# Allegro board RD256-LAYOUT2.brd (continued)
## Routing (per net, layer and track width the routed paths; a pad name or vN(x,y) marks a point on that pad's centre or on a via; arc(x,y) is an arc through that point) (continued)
SIG00045: length 1.3
  BOTTOM w0.3: R28.2 64.7,51.15 R27.1
SIG00046: length 3.9
  TOP w0.3: IC14.4 v2(62.25,52.53)
  BOTTOM w0.3: v2(62.25,52.53) 62.7,52.5 R33.2 R28.1
SIG00047: length 4.2
  TOP w0.3: v2(47,47.9) 46.52,47.9 46,47.38 IC15.4
  BOTTOM w0.3: R30.1 R34.2 v2(47,47.9)
SIG00048: length 1.3
  BOTTOM w0.3: R30.2 49.75,46.65 R35.1
SIG00049: length 1.3
  BOTTOM w0.3: R31.1 49.85,45.15 R35.2
SIG00067: length 4.7
  TOP w0.3: IC18.4 v2(38.57,9.15)
  BOTTOM w0.3: R49.1 39.17,9.75 v2(38.57,9.15) 38.12,9.2 R54.2
SIG00068: length 3.9
  TOP w0.3: R55.2 R51.1 78.45,16.5 78.8,16.15 IC19.4
SIG00069: length 1.2
  TOP w0.3: R56.1 77,14.95 R51.2
SIG00070: length 1.3
  TOP w0.3: R56.2 R52.1
SIG00080: length 2.8
  TOP w0.3: IC25.3 25.45,44.55 C77.2 25.65,44.35 R69.2
SIG00081: length 9.1
  TOP w0.3: R69.1 24.6,41.65 22.6,43.65 v2(22.6,46.1) ; v2(23.25,47.55) 24.01,47.55 24.15,47.69 IC25.6
  BOTTOM w0.3: v2(23.25,47.55) 23.25,46.75 v2(22.6,46.1)
SIG00082: length 1.4
  TOP w0.3: Q8.1 30.35,45.75 IC26.6
SIG00083: length 5.9
  TOP w0.3: IC26.1 27.9,45.75 28.1,45.95 28.1,46.85 26.4,48.55 25.65,48.55 25.45,48.35 IC25.4
SIG00085: length 21.6
  TOP w0.3: R68.1 R73.2 36,39.95 C75.2 36.95,40.1 37.94,41.09 42.17,41.09 43.78,42.7 45.4,42.7 46,42.1 50.7,42.1 51.55,42.95 51.55,43.85 51.2,44.2 IC24.3
SIG00086: length 4.7
  TOP w0.3: v2(51.5,47.8) R66.1 51.6,46.65 51.6,45.7 51.4,45.5 IC24.1
  BOTTOM w0.3: v2(51.5,47.8) 52,47.8 52.25,47.55 R71.2
SIG00087: length 21.4
  TOP w0.3: IC24.4 52.15,44.2 52,44.05 52,43.65 v2(52.35,43.3)
  BOTTOM w0.3: R70.2 39.55,37.75 41.95,37.75 44.45,40.25 44.45,41.25 45.3,42.1 51.15,42.1 v2(52.35,43.3)
SIG00088: length 1.2
  BOTTOM w0.3: R70.1 35.1,40.7 34.02,40.7
SIG00089: length 7.1
  BOTTOM w0.3: IC22.1 32.15,45.85 32.5,45.5 32.5,44.85 33,44.35 R67.1 32.95,43.3 32.95,42.25 C78.2 32.7,40.48 Q10.3
SIG00090: length 2.7
  BOTTOM w0.15: IC22.6 28.65,45.85 28.5,46 28.5,46.75 28.3,46.95 IC27.1
SIG00092: length 12.5
  BOTTOM w0.15: IC23.1 24.68,54.17 21.95,51.45 21.95,49 22.48,48.48 23.07,48.48 23.9,47.64 23.9,46.7 24.15,46.45 IC27.7
SIG00095: length 1.4
  BOTTOM w0.2: IC23.4 28.32,53.33 R72.1
SIG00096: length 5.9
  TOP w0.3: Q7.1 30.7,40.58 R65.1 30.7,42 31,42.3 31.6,42.3 31.85,42.55 D24.1 31.85,45.05 Q8.3
SIG00097: length 11.3
  TOP w0.5: TP39.1 29.05,56 30.08,56 30.6,55.48 v2(30.6,55)
  BOTTOM w0.5: v2(30.6,55) 30.6,54.1 R72.2 31.25,52.35 R74.2 33.85,52.35 Q9.1
SIG00098: length 3
  TOP w0.3: Q7.2 31.07,38.92 31.55,38.45 R68.2
SIG00099: length 4.2
  BOTTOM w0.3: C87.2 46.65,16.5 R79.2 47.75,16 47.95,15.8 48.45,15.8 48.65,15.6 48.65,15.35 48.45,15.15 IC31.3
SIG00100: length 3.4
  BOTTOM w0.15: R79.1 49.25,15.85 49.02,15.62 49.02,14.03 49.2,13.85 IC31.6
SIG00101: length 7.6
  BOTTOM w0.15: IC32.1 53.2,15.15 53.38,15.32 53.38,15.82 53.5,15.95 53.5,16.2
  BOTTOM w0.3: 53.5,16.2 53.5,16.8 53.2,17.1 51.45,17.1 50.9,16.55 50.9,15.55 50.5,15.15 IC31.4
SIG00102: length 3.1
  BOTTOM w0.15: IC32.6 55.4,15.15 56.45,16.2 Q12.1
SIG00104: length 13.8
  TOP w0.3: IC30.3 C86.2 R83.2 60,19.4 60.25,19.65 61.95,19.65 63.25,18.35 63.25,14.7 v2(62,13.45)
  BOTTOM w0.3: R78.1 v2(62,13.45)
SIG00105: length 2.7
  TOP w0.3: IC30.1 59.85,16.05 R76.1 R81.2
SIG00106: length 2.5
  TOP w0.3: IC30.4 54.6,17.35 R80.2
SIG00107: length 1.3
  TOP w0.3: Q14.1 52.67,17.07 R80.1
SIG00108: length 5.7
  TOP w0.3: C88.2 50.62,15.45 Q14.3 51.65,15.93 51.95,15.62 R77.1 IC28.1
SIG00109: length 2.4
  TOP w0.15: IC33.1 52.94,11.25 52.54,11.65 52.15,11.65 51.95,11.45 IC28.6
SIG00111: length 3.9
  TOP w0.3: IC33.7 v2(57.3,10.75)
  BOTTOM w0.2: IC29.1 55.9,9.35 v2(57.3,10.75)
SIG00114: length 1.1
  BOTTOM w0.15: IC29.4 54.17,7.72 R82.1
SIG00115: length 7.3
  BOTTOM w0.15: Q12.3 57.75,14.75 D25.1 58.8,13.85 58.8,11.35 R75.1 59.52,11.25 Q11.1
SIG00116: length 8
  TOP w0.3: TP40.1 56.45,7.8 v2(56.85,7.4)
  BOTTOM w0.5: R82.2 55.75,7.4 v2(56.85,7.4) 57.45,8 R84.2 58.65,7.3 Q13.1
SIG00117: length 1.3
  BOTTOM w0.3: Q11.2 60.77,10.95 R78.2
SIG00118: length 9
  TOP w0.15: IC34.2 43.58,36.33 R99.1 44.2,36.3 44.35,36.45 45.1,36.45 v2(45.58,36.92)
  BOTTOM w0.15: 48.08,38.83 48.08,38.27 47.9,38.1 47.3,38.1 46.77,37.58 IC36.3 46.77,36.27 46.65,36.15 46.1,36.15 45.86,36.39 v2(45.58,36.92)
SIG00119: length 4.2
  TOP w0.15: IC34.6 44.08,39.38 44.33,39.12 v2(45.58,39.12)
  BOTTOM w0.15: IC36.4 46.77,39.48 46.62,39.62 46.08,39.62 v2(45.58,39.12)
SIG00120: length 3.5
  TOP w0.15: IC37.1 47.77,37.83 47.77,36.83 C99.2 46.73,36.52 R99.2
SIG00121: length 13.3
  TOP w0.15: IC37.4 49.17,39.17 49.7,38.65 49.7,35.85 48.58,34.73 43.67,34.73 43.08,35.33 IC34.1
SIG00122: length 14.3
  TOP w0.15: TP30.1 v2(39.7,39.85) 39.7,38.7 40.58,37.83 43.83,37.83 44.08,37.58 IC34.3
  TOP w0.24: IC35.7 35.6,42.1 v2(35.25,41.75)
  BOTTOM w0.15: v2(35.25,41.75) 35.77,41.23 38.33,41.23 v2(39.7,39.85)
SIG00123: length 8
  TOP w0.15: IC34.5 44.58,40.42 45.1,40.95 v2(46.45,40.95) ; IC37.3 49.17,38.62 48.7,39.1 48.05,39.1 47.88,39.27 IC37.6 47.8,39.9 v2(47.8,40.95)
  BOTTOM w0.15: v2(46.45,40.95) v2(47.8,40.95)
SIG00124: length 11.2
  TOP w0.15: IC34.7 v2(43.58,40.92) TP32.1
  TOP w0.24: IC35.8 36.1,42.05 v2(36.4,41.75)
  BOTTOM w0.15: v2(43.58,40.92) 42.75,41.75 v2(36.4,41.75)
SIG00126: length 1.9
  TOP w0.24: R90.1 35.6,46.87 IC35.4
SIG00127: length 2.9
  TOP w0.24: v2(36.4,47.45) 36.1,47.15 IC35.3
  BOTTOM w0.24: C94.2 v2(36.4,47.45)
SIG00129: length 7.3
  TOP w0.24: R103.1 42.65,43.35 41.65,42.35 37.35,42.35 37.1,42.6 IC35.10
SIG00130: length 1.5
  TOP w0.5: Q16.3 41.95,46.4 R103.2
SIG00134: length 1.5
  BOTTOM w0.5: Q17.3 47.45,53.75 R104.2
SIG00136: length 1.5
  TOP w0.5: R90.2 33.12,47.05 32.35,47.05 Q15.3
SIG00138:
  vias: v1(2.5,42.65) v1(2.5,41.65) v1(3.5,42.65) v1(3.5,41.65)
SIG00141: length 4.6
  TOP w1.2: D28.2 8,58.2 P7.1
SIG00142: length 10.5
  TOP w0.15: IC40.6 84.35,6.7 84.58,6.47 85.45,6.47 85.65,6.28 IC40.3
  TOP w0.3: IC40.6 84.35,8.55 84.1,8.8 83.4,8.8 83,9.2 R119.1 ; IC40.3 v2(85.65,4.65)
  BOTTOM w0.3: IC38.2 84.15,5.99 84.36,6.2 84.94,6.2 85.3,5.84 85.3,5 v2(85.65,4.65)
SIG00143: length 17.9
  TOP w0.3: v2(85.65,2.4) 86.45,2.4 88.85,4.8 88.85,12.35 87.65,13.55 IC41.4
  BOTTOM w0.3: IC38.1 84.65,2.8 85.05,2.4 v2(85.65,2.4)
SIG00144: length 12.2
  TOP w0.15: TP35.1 v2(82.3,4.6)
  TOP w0.24: v2(76.5,6.45) 75.85,7.1 75.85,7.8 76,7.95 IC39.7
  BOTTOM w0.15: IC38.3 83.65,4.85 83.4,4.6 v2(82.3,4.6) 80.45,6.45 v2(76.5,6.45)
SIG00145: length 3.9
  TOP w0.3: IC40.4 v2(85.65,8.75)
  BOTTOM w0.3: IC38.6 83.65,8.7 84,9.05 85.35,9.05 v2(85.65,8.75)
SIG00146: length 4
  TOP w0.15: R119.2 C111.2 86.35,10 IC41.1
SIG00147: length 10.7
  TOP w0.15: IC41.3 87.65,12.95 87.12,13.47 86.53,13.47 86.35,13.65 IC41.6
  TOP w0.3: v2(88.05,11.15) 87.65,11.55 IC41.3
  BOTTOM w0.3: v2(88.05,11.15) 86.4,9.5 83.75,9.5 83.15,8.9 IC38.5
SIG00148: length 10.6
  TOP w0.15: v2(82.3,7.45) TP37.1
  TOP w0.24: IC39.8 v2(76.5,7.45)
  BOTTOM w0.15: v2(76.5,7.45) v2(82.3,7.45) 84,7.45 84.15,7.6 IC38.7
SIG00150: length 4.7
  TOP w0.24: R123.1 76.21,4.8 77.6,6.19 77.6,7.75 77.5,7.85 IC39.10
SIG00151: length 4.8
  TOP w0.24: IC39.4 76,13.45 74.85,14.6 R110.1
SIG00152: length 3
  TOP w0.24: v2(76.8,12.3) 76.5,12 IC39.3
  BOTTOM w0.3: C106.2 77.62,12.55 77.38,12.3 v2(76.8,12.3)
SIG00154: length 2.2
  TOP w0.5: Q19.3 73.55,5.55 R123.2
SIG00155: length 1.4
  TOP w0.5: Q18.3 R110.2
SIG00160: length 1.5
  BOTTOM w0.5: Q20.3 R124.2
SIG00162:
  vias: v1(2.5,17.9) v1(2.5,16.9) v1(3.5,17.9) v1(3.5,16.9)
SIG00166: length 3.7
  TOP w0.3: 13.8,40.92 14.43,40.92 14.65,41.15 R126.1 14.75,42.7 R178.2
SIG00167: length 8
  TOP w0.3: R131.2 21.9,35.55 19.55,35.55 19.1,36 Q21.5 19.1,37.2 18.45,37.85 Q21.2 18.45,39.27 C116.1
SIG00168: length 2.7
  TOP w0.3: R133.2 R131.1
SIG00169: length 6.2
  BOTTOM w0.3: R129.1 R132.2 17.23,43.67 C120.2 16.45,41.62 16.45,40.7 16.93,40.23 IC51.3
SIG00170: length 8.3
  TOP w0.3: R179.2 33.65,36.4 32.25,37.8 28.4,37.8 28.25,37.65 R127.1 28.02,36.88 Q23.1
SIG00171: length 3
  TOP w0.3: D40.2 28.07,35.73 Q23.3 26.73,35.65 R135.2
SIG00172: length 16.2
  TOP w0.3: R128.1 D40.1 29.85,35.05 29.45,34.65 24.55,34.65 22.82,36.38 v2(22.82,38.95)
  BOTTOM w0.3: IC51.6 22.7,40.23 C121.2 v2(22.82,38.95)
SIG00173: length 2.7
  BOTTOM w0.3: R125.1 23.9,44.3 24.25,43.95 R130.2
SIG00174: length 4
  BOTTOM w0.3: R130.1 R134.2 21.93,40.88 IC51.5
SIG00175: length 2.2
  TOP w0.3: R136.1 20.35,43.8 19.95,43.4 Q24.1
SIG00176: length 52.9
  TOP w0.3: IC48.1 v2(57.65,35.35)
  BOTTOM w0.3: v2(57.65,35.35) 55.95,33.65 15.75,33.65 14.15,35.25 R137.1 14.15,37.45 C128.2 14.1,38.3 14.72,38.92 IC51.1
SIG00177: length 1.3
  TOP w0.3: Q25.1 38.65,37.2 R138.1
SIG00178: length 3
  BOTTOM w0.3: 20.4,39.58 21.07,39.58 R143.2
SIG00179: length 43.2
  TOP w0.3: IC43.1 57.75,39.75 58,39.5 59.5,39.5 v2(59.9,39.1)
  BOTTOM w0.3: R143.1 25.45,37.9 R139.1 26.8,37.85 C130.2 27.1,37 29.95,34.15 48.75,34.15 51.95,37.35 58.15,37.35 v2(59.9,39.1)
SIG00180: length 1.2
  TOP w0.3: R140.1 R142.2
SIG00181: length 5.9
  TOP w0.3: IC50.3 74.47,37.88 74.2,37.6 74.2,36.6 73.97,36.38 C131.2 73.17,36.3 R147.2 R142.1
SIG00182: length 7
  TOP w0.3: IC50.6 78.1,37.88 76.95,36.73 R146.2 76.5,35.7 76.2,36 76.2,36.92 75.9,37.23 IC50.4
SIG00183: length 4
  TOP w0.3: R148.2 78.55,35.6 R146.1 78.45,36.95 78.72,37.23 IC50.5
SIG00184: length 1.8
  TOP w0.15: IC49.2 60.55,36.55 60.4,36.4 60.4,36.19 60.54,36.05 IC49.3
SIG00185: length 2.6
  TOP w0.3: IC50.8 78.92,39.17 78.7,39.4 78.7,39.7 R144.2
SIG00186: length 39.1
  TOP w0.3: R144.1 81.15,40.55 C132.2 82.1,39 83.65,37.45 83.65,34.95 82.85,34.15 54.8,34.15 53.75,35.2 IC45.1
SIG00187: length 7.9
  TOP w0.15: IC47.3 56.91,49.45 55.55,50.81 55.55,52.85 54.7,53.7 53.57,53.7 53.42,53.84 IC53.1
SIG00191: length 31.1
  TOP w0.15: 59.2,41.2 v2(59.9,41.2) ; 59.2,41.2 59.05,41.05 ; 59.2,41.2 59.05,41.2 ; 59.05,41.05 IC43.3 ; 59.05,41.05 59.05,41.2 ; 59.05,41.2 58.75,41.5 57.9,41.5 57.75,41.65 IC43.6
  TOP w0.3: R138.2 40.25,34.1 49.6,34.1 v2(50.8,35.3)
  BOTTOM w0.3: v2(59.9,41.2) 60.6,40.5 60.6,38.95 58.4,36.75 52.25,36.75 v2(50.8,35.3)
SIG00192: length 3.1
  TOP w0.15: IC46.1 60.58,41.15 60.42,41.3 60.42,41.52 60.23,41.73 59.62,41.73 59.45,41.55 59.19,41.55 59.05,41.69 IC43.4
SIG00193: length 2.8
  TOP w0.15: IC45.6 53.75,37.65 53.88,37.52 54.48,37.52 55.05,36.95 IC45.3
SIG00194: length 16.1
  TOP w0.15: IC45.4 55.05,37.55 55.6,37 55.6,35.65 56.45,34.8 58.95,34.8 v2(59.5,35.35) ; IC49.1 v2(60.1,37.05) ; IC46.2 v2(62,40.65)
  BOTTOM w0.15: v2(59.5,35.35) 59.5,36.45 v2(60.1,37.05) 60.95,37.05 62,38.1 v2(62,40.65)
SIG00195: length 2.8
  TOP w0.15: IC48.3 58.95,37.05 58.48,37.52 57.88,37.52 57.65,37.75 IC48.6
SIG00196: length 1.7
  TOP w0.15: IC42.2 60.49,44.75 60.35,44.61 60.35,44.4 60.5,44.25 IC42.3
SIG00197: length 15.8
  TOP w0.15: IC42.6 63.24,44.25 63.1,44.39 63.1,44.6 63.25,44.75 IC42.7 64.25,44.75 64.42,44.92 64.42,46.75 62.52,48.65 v2(61.95,48.65) 61.65,48.95 IC47.5 ; IC47.1 57.65,50.45 v2(57.1,51)
  BOTTOM w0.15: v2(61.95,48.65) 59.45,48.65 v2(57.1,51)
SIG00198: length 9.5
  TOP w0.15: IC42.5 64.85,43.75 65.55,43.05 65.55,41.4 v2(64.8,40.65) IC46.7 ; TP45.1 v2(66.75,40.65)
  BOTTOM w0.15: v2(66.75,40.65) v2(64.8,40.65)
SIG00199: length 10.7
  TOP w0.15: TP46.1 65.95,35.55 IC49.5 62.9,35.55 62.3,34.95 60.65,34.95 59.5,36.1 59.5,37 58.95,37.55 IC48.4
SIG00200: length 10.7
  TOP w0.15: IC44.4 56.75,44.7 57.3,44.15 57.85,44.15 59.02,42.98 59.62,42.98 59.9,42.7 v2(59.9,42.25) ; IC46.5 v2(62.7,39.65)
  BOTTOM w0.15: v2(62.7,39.65) 62.7,40.7 62,41.4 60.75,41.4 v2(59.9,42.25)
SIG00201: length 1.6
  BOTTOM w0.15: 23.95,11.32 23.95,11.81 24.1,11.96 24.31,11.96 24.45,11.82 24.45,11.32
SIG00202: length 10.7
  TOP w0.15: v2(22.7,11.8) 22.15,12.35 22.15,13.4 22.35,13.6 22.9,13.6 23.15,13.35 23.8,13.35 23.95,13.5 IC58.7 23.95,14.65 23.75,14.85 23.75,15.4 TP47.1
  BOTTOM w0.15: v2(22.7,11.8) 22.7,10.97 23.45,10.22 IC55.5
SIG00203: length 2.7
  TOP w0.3: R183.2 R151.1 9.3,18.15 Q28.1
SIG00205: length 2.8
  BOTTOM w0.3: R156.1 R158.2
SIG00206: length 6.1
  TOP w0.3: IC64.3 v2(9.07,12.68)
  BOTTOM w0.3: R154.1 R157.2 11.28,10.88 C140.2 9.07,11.8 v2(9.07,12.68)
SIG00207: length 4
  BOTTOM w0.3: R184.2 R152.1 13.07,3.88 Q29.1
SIG00208: length 4.6
  TOP w0.3: D41.2 v2(12.1,5)
  BOTTOM w0.3: v2(12.1,5) 10.03,5 Q29.3 R160.2
SIG00209: length 5.5
  TOP w0.3: IC64.6 9.07,7.78 8.4,7.1 8.4,6.72 C141.2 9.47,6.53 R153.1 9.65,6.7 D41.1
SIG00210: length 1.3
  BOTTOM w0.3: R155.2 R150.1
SIG00211: length 4.5
  TOP w0.3: v2(8,7.6) 8.43,8.03 IC64.5
  BOTTOM w0.3: R155.1 v2(8,7.6) R159.2
SIG00212: length 1.5
  BOTTOM w0.3: R161.1 15.35,13.7 15,13.7 14.6,13.3 Q30.1
SIG00214: length 1.6
  BOTTOM w0.3: Q31.1 R163.1
SIG00215: length 13.7
  TOP w0.3: v2(15.3,14.85) 15.25,14.4 15.25,12 13.4,10.15 13.4,7.9 13.05,7.55 10.25,7.55 9.72,8.07 IC64.7
  BOTTOM w0.3: R168.2 16.05,14.85 v2(15.3,14.85)
SIG00216: length 7.8
  BOTTOM w0.3: IC54.1 20.6,19.48 20.32,19.75 19,19.75 C150.2 17.65,17.9 R164.1 R168.1
SIG00217: length 1.3
  BOTTOM w0.3: R165.1 R167.2
SIG00218: length 4
  BOTTOM w0.3: IC63.3 34.3,16.1 R167.1 34.4,16.2 R172.2 35.67,17.4 35.75,17.48
SIG00219: length 6.1
  BOTTOM w0.3: 31.6,15.45 R171.2 ; 31.6,15.45 30.95,16.1 IC63.6 ; 31.6,15.45 IC63.4
SIG00220: length 4
  BOTTOM w0.3: IC63.5 29.6,15.45 30.1,14.95 R171.1 30,13.9 R173.2
SIG00221: length 10
  TOP w0.15: v2(22.85,18.43) 22.45,18.02 TP48.1
  BOTTOM w0.15: v2(22.85,18.43) 23.45,17.82 IC61.5 23.45,13.45 23.35,13.35 23.35,12.75 23,12.4 22.05,12.4 21.9,12.25 21.9,11.72
SIG00222: length 3.5
  BOTTOM w0.3: IC63.8 28,17.4 27.75,17.65 27.75,19.15 27.5,19.4 R169.2
SIG00223: length 6.8
  TOP w0.3: v2(28.57,14.62) 29.6,14.62 30.05,14.18 IC57.1
  BOTTOM w0.3: R169.1 26.9,16.65 C152.2 27.6,15.45 27.6,14.9 27.88,14.62 v2(28.57,14.62)
SIG00224: length 7.2
  TOP w0.15: 22.6,3.98 22.6,4.86 22.89,5.15 25,5.15 25.5,5.65 25.5,6.9 25.2,7.2 24.65,7.2 24.45,7 24.45,6.42
SIG00228: length 11
  TOP w0.3: v2(20.6,15.55) 20.6,15.1 v2(17.8,12.3)
  BOTTOM w0.15: IC54.6 20.6,17.18 20.79,17.38 21.3,17.38 21.9,17.98 IC54.3
  BOTTOM w0.3: IC54.6 v2(20.6,15.55) ; v2(17.8,12.3) 17.8,10.7 R163.2
SIG00229: length 6
  TOP w0.15: 23.45,11.32 23.45,12.2 v2(22.7,12.95)
  BOTTOM w0.15: v2(22.7,12.95) 22.7,14.95 21.9,15.75 IC54.4
SIG00230: length 1.6
  BOTTOM w0.15: 24.45,6.42 24.45,5.95 24.3,5.8 24.1,5.8 23.95,5.95 23.95,6.42
SIG00231: length 6.4
  TOP w0.15: IC59.5 24.95,8.55 24.55,8.15 v2(23.95,8.15) 23.45,7.65 23.45,6.42
  BOTTOM w0.15: IC55.7 24.45,9.7 24.3,9.85 24.08,9.85 23.95,9.72 IC55.6 v2(23.95,8.15)
SIG00232: length 12.1
  TOP w0.15: IC58.5 24.95,13.5 25.1,13.35 v2(27.75,13.35) ; v2(27.85,9.3) 27.3,8.75 27.3,7.55 27.5,7.35 28.15,7.35 28.3,7.5 28.6,7.5 28.75,7.35 IC56.4
  BOTTOM w0.15: v2(27.75,13.35) 28.4,12.7 28.4,9.85 v2(27.85,9.3)
SIG00233: length 2.8
  TOP w0.15: IC57.6 30.05,12.2 29.82,12.43 29.27,12.43 28.75,12.95 IC57.3
SIG00234: length 9.4
  TOP w0.15: 23.95,11.32 v2(23.95,12.7) 24.3,13.05 27.15,13.05 27.4,12.8 28.4,12.8 28.75,12.45 IC57.4
  BOTTOM w0.15: v2(23.95,12.7) 24.4,12.7 24.95,12.15 24.95,11.32
SIG00235: length 2.7
  BOTTOM w0.15: 20.6,11.72 20.6,12.26 20.79,12.45 21.3,12.45 21.9,13.05 IC60.3
STO_VMOS_A: length 14.1
  TOP w0.15: v2(51.5,53.1) 51.5,50.75 52.85,49.4 TP43.1 54.3,48.1 56.23,46.17 57.91,46.17 58.05,46.03 IC44.6
  BOTTOM w0.15: R104.1 v2(51.5,53.1)
STO_VMOS_B: length 46.2
  TOP w0.3: TP44.1 65.75,18.2 v2(66.4,18.85) ; v2(30.95,7.45) 30.5,7.45 30.05,7 IC56.6
  BOTTOM w0.3: v2(66.4,18.85) R124.1 65.4,19.5 65,19.9 63.25,19.9 60.95,17.6 50.8,17.6 50.6,17.4 42.43,17.4 35.33,10.3 31.55,10.3 30.95,9.7 v2(30.95,7.45)
VE_A: length 44.3
  TOP w0.3: Q23.2 26.12,37.15 R135.1 ; 13,40.92 13,41.65
  TOP w0.5: R133.1 21.05,41.45 v1(20.1,42.4) ; IC17.3 75.8,45.75 75.45,45.4 75.45,44.2 75.8,43.85 IC17.1 ; v1(24.15,38.95) 25.2,37.9 R135.1
  TOP w1: CN2.4 55.43,59.8 ; CN2.4 CN2.3 ; CN2.4 55.43,57.55 ; 57.97,59.8 CN2.3 ; CN2.3 57.97,57.45 ; CN2.3 58.85,58.7
  CONDUCTIVE2 w0.3: CN2.3 CN2.4 ; CN2.3 59.15,58.7 ; CN2.3 57.97,60.1 ; CN2.3 57.97,57.4 ; CN2.4 55.43,57.25 ; CN2.4 54.1,58.7 ; CN2.4 55.43,60.3 ; P5.1 34.5,60.2 ; P5.1 32.86,58.45 ; P5.1 31.05,60.2
  BOTTOM w0.5: R132.1 18.65,42.48 C120.1 v1(20.1,42.4) ; v1(24.15,38.95) 24.18,39.55 C121.1 24.25,40.42 R134.1 ; R33.1 64.75,53.3 64.45,53.6 v1(61.7,53.6)
  vias: v1(2.5,36.4) v1(2.5,35.4) v1(3.5,36.4) v1(3.5,35.4) v1(5.15,43.2) v1(6.15,43.2) v1(10.15,43.5) v1(10.15,42.5) v1(11.15,43.5) v1(11.15,42.5) v1(25,53.3) v1(25,52.3) v1(27.3,59.6) v1(28.3,59.6) v1(28.5,55) v1(29.3,59.6) v1(29.5,55) v1(30.3,59.6) v1(41.7,55.85) v1(41.7,54.85) v1(42.7,55.85) v1(42.7,54.85) v1(60.5,53.6) v1(68.25,58.75) v1(68.25,57.75) v1(69.45,58.75) v1(69.45,57.75) v1(70.85,49.35) v1(70.85,48.35) v1(71.85,49.35) v1(71.85,48.35) v1(79.8,43.2) v1(79.8,42.2) v1(80.8,43.2) v1(80.8,42.2) v1(87.2,43.2) v1(87.2,38.2) v1(87.2,35.4) v1(92.2,43.2) v1(92.2,38.2) v1(92.2,35.4) v1(97.2,43.2) v1(97.2,38.2) v1(97.2,35.4)
VE_B: length 46.1
  TOP w0.3: v1(6.45,17.15) 6.78,16.82 Q28.2
  TOP w0.5: 52.3,7.2 52.3,8.7 51.85,9.15 IC21.3 ; C141.1 8.2,4.44 v1(8,3.88)
  TOP w1: CN3.3 38.23,2.3 ; CN3.3 CN3.4 ; CN3.3 38.23,4.35 ; CN3.3 37.15,3.25 ; CN3.4 40.77,2.25 ; CN3.4 40.77,4.2
  CONDUCTIVE2 w0.3: CN3.4 40.77,4.45 ; CN3.4 CN3.3 ; CN3.4 40.77,2.1 ; CN3.4 42,3.25 ; CN3.3 38.23,2 ; CN3.3 36.9,3.25 ; CN3.3 38.23,4.5 ; P12.1 65.65,1.8 ; P12.1 61.55,1.8 ; P12.1 63.34,3.5
  CONDUCTIVE3 w1: P12.1 63.34,3.5 ; P12.1 66.3,1.8 ; P12.1 62,1.8
  BOTTOM w0.3: Q29.2 v1(8,3.88)
  BOTTOM w0.5: v1(11.5,19.2) R158.1 ; R159.1 v1(8,3.88) ; R160.1 C140.1 10.07,9.45 R157.1 11.4,9.4 v1(11.4,8.35) ; R54.1 v1(37.25,6.6)
  BOTTOM w0.8: v1(37.25,5.6) v1(37.25,6.6)
  vias: v1(2.55,7.95) v1(3.55,7.95) v1(5.45,18.15) v1(5.45,17.15) v1(6.45,18.15) v1(6.45,8.5) v1(6.45,7.5) v1(36.95,19.4) v1(36.95,18.2) v1(37.95,19.4) v1(37.95,18.2) v1(52.35,5.2) v1(53.35,6.2) v1(53.35,5.2) v1(54.35,5.2) v1(74.05,3.65) v1(74.05,2.45) v1(75.05,3.65) v1(75.05,2.45) v1(97.6,19.6) v1(97.6,14.6) v1(97.6,9.6)
VGATE_A: length 7.1
  TOP w0.3: Q7.3 32.23,41.38 R65.2 32.2,41.75 32.7,42.25 32.7,45.15 v2(33.1,45.55)
  BOTTOM w0.5: C94.1 38.83,48.4
  vias: v2(33.1,46.35) v2(33.9,46.35) v2(33.9,45.55) v2(35.75,51.8) v2(35.75,51) v2(35.75,50.2) v2(35.75,49.4) v2(36.55,51.8) v2(36.55,51) v2(36.55,50.2) v2(36.55,49.4)
VGATE_B: length 5.3
  TOP w1: 59.53,4.02 59.53,5.15
  BOTTOM w0.3: 61.65,9.72 60.3,9.72 60.27,9.75 R75.2
  BOTTOM w0.5: v1(75.1,13.35) 75.15,13.4 C106.1
  vias: v1(74.1,13.35) v1(74.1,12.35) v1(75.1,12.35) v2(61.65,9) v2(61.65,8.2) v2(62.45,9) v2(62.45,8.2) v2(63.25,9) v2(63.25,8.2) v2(64.05,9) v2(64.05,8.2)
VGD_A: length 7.8
  TOP w0.5: TP12.1 49.65,48.4 49.65,44.3 49.35,44 v2(48.6,44)
  BOTTOM w0.5: R31.2 48.2,44
  vias: v2(40.55,45.85) v2(40.55,45.05) v2(41.35,45.85) v2(41.35,45.05) v2(47.8,44) v2(47.8,43.2) v2(48.6,43.2)
VGD_B: length 0.9
  TOP w0.3: R52.2 80.92,12.55
VL_A: length 116.8
  TOP w0.2: C24.1 56.52,54.75 IC7.5 ; C124.1 52.58,53.08 IC53.5
  TOP w0.3: C100.2 47.08,40.4 47.08,41.08 47.55,41.55 48.05,41.55 48.52,41.08 IC37.5 ; IC25.5 24.8,48.25 24.5,48.55 22.38,48.55 22.3,48.48 ; C117.2 63.3,42.17 63.3,41.35 63.5,41.15 IC46.8 ; IC43.5 58.4,42.85 58.15,43.1 57.35,43.1 56.52,42.27 C114.1 ; IC47.8 60.42,50.45 60.27,50.6 C118.2 ; C93.2 41.92,40.38 42.17,40.62 42.83,40.62 43.08,40.38 IC34.8 ; IC45.5 54.4,38.8 54.15,39.05 53.27,39.05 C119.1 ; IC48.5 58.3,38.75 58,39.05 57.17,39.05 C122.1 ; 79.62,38.52 78.65,38.52 78.03,39.15 C126.2 ; IC26.5 28.55,45.1 28.35,44.9 28.35,43.33 C69.2 ; IC42.8 63.5,45.25 63.3,45.45 63.3,46.23 63.48,46.4 ; C123.2 63.15,38.08 63.15,37.2 63.3,37.05 IC49.8 ; C115.1 59.23,44.55 57.65,44.55 57.4,44.8 IC44.5 ; C74.2 54.12,45.65 53.52,45.65 53.38,45.5 IC24.5
  TOP w0.5: v1(55.17,42.35) 56.33,42.35 C114.1 ; C122.1 v1(55.17,39.5) ; C115.1 v1(59.4,43.75) ; C118.2 60.27,52.33 59.9,52.7 v1(58.9,52.7) 58.9,53.15 57.77,54.27 C24.1 ; C119.1 51.95,38.83 v1(51.95,39.45) ; R140.2 70.6,43.65 TP14.1 ; v1(40.92,39.83) 41.52,39.85 C93.2 ; v1(28.3,42.15) 28.48,42.72 C69.2 ; R66.2 53.25,47 v1(54.25,47) 54.25,45.88 C74.2 ; v1(45.6,40.25) 46.33,40.25 C100.2 ; 22.3,48.48 22.3,49.05 v1(22.7,49.45) ; C117.2 v1(64.8,42.3) ; C126.2 78.03,41.38 77.5,41.9 74.2,41.9 ; C124.1 v1(52.8,51.65) ; 63.48,46.4 63.48,47.02 63.05,47.45 v1(62.25,47.45) ; C123.2 v1(64.45,38.2)
  TOP w0.8: v1(28.3,42.15) 28.3,41.7 26.65,40.05 v1(26.65,39.65) ; v1(52.8,50.65) v1(52.8,51.65)
  CONDUCTIVE3 w1: 45.35,35.3 47.3,37.25 ; 48.95,37.1 48.95,34.8 47.9,33.75 46.86,33.75 ; 21.7,42.5 21.7,43.75 19.85,45.6 19.85,48.2 20.36,48.71
  BOTTOM w0.2: IC23.5 26.5,52.55 C71.2
  BOTTOM w0.3: C73.2 25.43,47.2 25.18,46.95 IC27.8 ; R67.2 31.5,42.45 30.35,41.3 29.15,41.3 v1(28.3,42.15) ; IC36.5 47.42,39.45 47.73,39.75 C96.2 ; IC22.5 28.76,45.2 28.45,44.89 28.45,43.73 C70.2
  BOTTOM w0.5: C96.2 v1(49.33,40.95) ; C71.2 26.77,52.27 C72.2 26.13,50.9 25.68,51.35 23.7,51.35 22.7,50.35 v1(22.7,49.45) 23.16,49.06 24.11,48.1 C73.2 ; C70.2 28.3,42.73 v1(28.3,42.15) ; R137.2 v1(16.8,36.1) ; R139.2 25.8,39.65 v1(26.65,39.65)
  vias: v1(68,42.8) v1(68,41.8) v1(69,42.8) v1(69,41.8)
VL_B: length 139.1
  TOP w0.2: C28.1 26.6,4.58 IC11.5 ; IC65.5 23.98,3.12 C144.1
  TOP w0.3: C80.2 50.9,11.82 51.3,11.43 IC28.5 ; IC41.5 87,14.85 86.7,15.15 85.97,15.15 85.05,14.22 ; IC59.8 23.45,8.55 23.2,8.3 22,8.3 C138.2 ; IC40.5 85,7.05 85.2,6.85 86.88,6.85 C108.2 ; C84.2 56.77,15.18 57.15,15.55 57.15,15.8 56.9,16.05 IC30.5 ; IC33.8 55.67,11.25 55.48,11.45 55.48,12.4 ; IC57.5 29.4,11 29.6,10.8 30.62,10.8 C139.1 ; IC58.8 23.45,14.5 23.25,14.7 22.3,14.7 21.45,13.85 C137.2 ; IC56.5 29.4,6.25 29.75,5.9 30.6,5.9 30.9,6.2 30.9,6.55 31.43,7.08 C135.1
  TOP w0.5: 55.48,12.4 55.48,12.81 v1(55.6,13.4) ; C138.2 v1(20.65,8.45) ; C137.2 20.14,13.38 19,12.24 v1(19,10.8) ; C144.1 24.1,2.8 23.7,2.4 v1(23.1,2.4) ; R76.2 v1(59.9,13.4) ; C139.1 32.4,11.97 v1(33.1,12.68) ; R77.2 54.6,14.7 ; C80.2 v1(49.4,10.8) ; C28.1 v1(26.4,5.55) ; v1(55.6,14.4) 56.15,14.65 C84.2 ; C108.2 v1(88.12,6.67) ; C135.1 v1(32.1,5.9) ; 85.05,14.22 v1(83.85,14.22)
  TOP w0.8: v1(20.65,8.45) v1(19.65,8.45) 19.65,8.15 18.55,7.05 15.1,7.05 14.15,8 v1(14.15,8.35)
  TOP w1: 47.4,3.25 CN3.7 48.39,4.5
  CONDUCTIVE3 w1: 35.01,16.5 45.91,16.5
  BOTTOM w0.15: C82.2 54.17,10.55 IC29.5
  BOTTOM w0.3: C134.1 19.68,16.43 19.95,16.15 19.95,15.15 20.2,14.9 20.9,14.9 21.25,15.25 IC54.5 ; IC55.8 24.95,8.6 25.15,8.4 25.5,8.4 25.85,8.75 C133.2 ; IC31.5 50.4,14.5 50.6,14.3 50.6,12.43 50.58,12.4 ; C105.2 86.3,7.47 84.9,7.47 84.65,7.72 IC38.8 ; C143.2 25.15,13.35 24.95,13.55 IC61.8 ; IC63.7 29.65,16.75 30.23,17.32 C146.2 ; 21.25,11.72 21.25,11.1 21.05,10.9 20.25,10.9 19.95,11.2 19.95,11.65 19.62,11.97 C142.1 ; 53.98,13.7 53.75,13.93 53.75,15.55 54,15.8 IC32.5
  BOTTOM w0.5: C146.2 29.65,19.18 v1(29.05,19.2) ; v1(88.12,6.67) 87.22,7.58 C105.2 ; v1(49.4,10.8) 50.23,10.8 50.58,11.15 50.58,12.4 ; C143.2 v1(26.75,14.55) ; v1(33.1,12.68) 34.35,13.93 R165.2 ; C82.2 54.12,11.97 C81.2 54.1,13.57 53.98,13.7 55.3,13.7 v1(55.6,13.4) ; C134.1 19,15.64 v1(19.1,15.05) 18.51,15.15 R164.2 ; v1(14.15,8.35) 14.15,9.3 R162.2 ; C142.1 v1(19,10.8) ; C133.2 v1(26.5,9.95)
  BOTTOM w0.8: v1(19.65,8.45) 19.45,8.25 19.45,6.05 v1(23.1,2.4) 27.8,2.4 31.3,5.9 v1(32.1,5.9) ; v1(19.65,8.45) 19,9.1 v1(19,10.8) ; v1(19.65,8.45) v1(20.65,8.45) ; v1(88.12,6.67) v1(89.6,6.67)
  vias: v1(45.1,5.85) v1(45.1,4.85) v1(46.1,5.85) v1(46.1,4.85)
N03856: length 8.4
  TOP w1: CN2.2 60.51,56.85 ; CN2.2 CN2.1 ; CN2.2 60.51,59.75 ; CN2.1 64,58.7 ; CN2.1 63.05,57.7 ; CN2.1 63.05,59.7
N502328: length 7
  TOP w1: CN3.2 35.69,2.25 ; CN3.2 CN3.1 ; CN3.2 35.69,4.4 ; CN3.1 33.15,2.3 ; CN3.1 33.15,4.6
N679544: length 1.3
  BOTTOM w0.3: R49.2 R48.1
N855499: length 12.1
  TOP w0.15: v2(60.55,46) 60.55,45.55 60.85,45.25 IC42.1 ; IC7.4 55.92,51.17 v2(57.1,50) 57.55,49.95 IC47.2
  BOTTOM w0.15: v2(60.55,46) 60.55,46.55 v2(57.1,50)
N871149: length 11
  TOP w0.15: 23.95,6.42 23.95,7.12 24.38,7.55 25.85,7.55 v2(27.85,5.55) 28.6,4.8 IC11.4
  BOTTOM w0.15: 24.95,6.42 24.95,5.9 25.95,4.9 27.2,4.9 v2(27.85,5.55)
N871259: length 7.5
  TOP w0.3: v2(14.4,16) Q27.5 16.2,16 16.85,16.65 Q27.2
  BOTTOM w0.3: v2(14.4,16) 13.95,16.02 C136.1 10.78,16.02 R156.2
N872651: length 15.6
  TOP w0.3: v2(13.7,11.75) 12.7,12.75 10.9,12.75 10.38,12.22 IC64.1
  BOTTOM w0.3: v2(13.7,11.75) 14,11.45 R162.1 C148.2 16.4,10.95 17.1,11.65 17.1,14 17.45,14.35 20.4,14.35 20.6,14.15 IC60.1
N1924743: length 1.6
  TOP w0.15: R176.1 19.1,39.9 Q21.1
N1924835: length 2.6
  TOP w0.15: R175.1 16.9,39.4 17.6,39.4 17.8,39.2 Q21.3
N1941594: length 1.2
  TOP w0.3: Q24.3 R178.1
N1941665: length 1.8
  TOP w0.3: R179.1 Q25.3
N1965883: length 1.5
  TOP w0.15: Q27.1 18.75,16 R181.1
N1966369: length 2.3
  TOP w0.15: R180.1 16.15,17.75 16.6,17.3 Q27.3
N1966980: length 4.7
  TOP w0.3: Q21.4 17.8,35.7 17.4,35.3 16.45,35.3 R177.2
N1967040: length 3.2
  TOP w0.3: Q27.4 R182.2
N1967770: length 2.9
  BOTTOM w0.3: R184.1 17.3,5.2 Q31.3
N1967776: length 13.1
  TOP w0.3: R183.1 7.85,20 8.05,20.2 13.1,20.2 v2(14.1,19.2)
  BOTTOM w0.3: v2(14.1,19.2) 14.1,17.4 15.1,16.4 15.1,15.6 14.2,14.7 Q30.3

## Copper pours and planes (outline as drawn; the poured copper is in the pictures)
VCC20_A on TOP: 47.75,50.65 47.62,50.68 47.53,50.77 47.5,50.9 47.5,56.5 47.53,56.62 47.62,56.72 47.75,56.75 50.8,56.75 50.92,56.72 51.02,56.62 51.05,56.5 51.05,50.9 51.02,50.77 50.92,50.68 50.8,50.65
VCC20_A on TOP: 26.53,50.01 26.44,50.05 26.34,50.01 26.3,49.91 26.3,49.11 26.28,49.05 26.23,49.01 26.19,49 26.15,49 23.85,49 23.78,49.03 23.75,49.1 23.75,50.95 23.78,51.08 23.88,51.17 24,51.2 25.3,51.2 25.58,51.32 25.7,51.6 25.7,52.1 25.73,52.17 25.8,52.2 31,52.2 31.07,52.17 31.1,52.1 31.1,50.58 31.15,50.38 31.22,50.3 31.57,49.95 31.59,49.91 31.6,49.88 31.6,46.85 31.57,46.73 31.48,46.63 31.35,46.6 28.5,46.6 28.43,46.63 28.4,46.7 28.4,46.85 28.38,46.96 28.31,47.06 26.6,48.77 26.58,48.8 26.57,48.84 26.57,49.91 ; 1 cut-out
VCC20_A on BOTTOM: 29.05,56.6 28.93,56.63 28.83,56.73 28.8,56.85 28.8,58.15 28.83,58.27 28.93,58.37 29.05,58.4 31.4,58.4 31.52,58.37 31.62,58.27 31.65,58.15 31.65,56.85 31.62,56.73 31.52,56.63 31.4,56.6
VCC20_A on BOTTOM: 50.35,57.7 51.06,57.99 51.35,58.7 51.35,60.35 51.42,60.53 51.6,60.6 63.25,60.6 63.34,60.58 63.42,60.53 67.83,56.12 67.88,56.04 67.9,55.95 67.9,46.3 67.87,46.17 67.78,46.08 67.65,46.05 65.5,46.05 65.38,46.08 65.28,46.17 65.25,46.3 65.25,52.04 65.25,52.07 65.29,52.17 65.3,52.25 65.3,53.45 65.27,53.57 65.23,53.62 63.97,54.88 63.86,54.94 63.8,54.95 54.72,54.95 54.69,54.95 54.46,55.07 54.25,55.1 54.04,55.07 53.81,54.95 53.78,54.95 49.65,54.95 49.37,55.07 49.25,55.35 49.25,57.45 49.32,57.63 49.5,57.7 ; 6 cut-outs
VCC20_A on CONDUCTIVE3: outline of 146 points within 12.7,35.25 67.35,61 ; 3 cut-outs
VCC20_B on TOP: 40.35,5 40.17,5.07 40.1,5.25 40.1,8.85 39.52,9.43 39.47,9.51 39.45,9.6 39.45,11 39.52,11.18 39.7,11.25 42.1,11.25 42.16,11.24 42.27,11.18 44.38,9.07 44.43,8.99 44.45,8.9 44.45,7.85 44.38,7.67 44.2,7.6 42.65,7.6 42.56,7.58 42.48,7.53 42.12,7.17 42.07,7.09 42.05,7 42.05,5.25 41.98,5.07 41.8,5
VCC20_B on TOP: 69.5,8.75 69.32,8.82 69.25,9 69.25,12.3 69.3,12.45 69.43,12.54 69.47,12.55 69.5,12.57 69.53,12.59 69.57,12.59 69.6,12.59 70.2,12.59 70.41,12.68 70.5,12.89 70.5,18.9 70.52,18.99 70.57,19.07 73.93,22.43 74.01,22.48 74.1,22.5 80.55,22.5 80.65,22.48 80.73,22.43 82.07,21.08 82.09,21.05 82.1,21.01 82.1,19 82.07,18.88 81.97,18.78 81.85,18.75 81.05,18.75 80.92,18.78 80.83,18.88 80.8,19 80.8,20.3 80.78,20.39 80.73,20.47 80.12,21.08 80.04,21.13 79.95,21.15 74.75,21.15 74.53,21.11 74.35,20.98 71.87,18.5 71.82,18.42 71.8,18.32 71.8,12.89 71.89,12.68 72.1,12.59 72.7,12.59 72.75,12.59 72.82,12.56 72.85,12.49 72.85,9 72.78,8.82 72.6,8.75
VCC20_B on BOTTOM: 71.6,6.3 71.47,6.33 71.38,6.42 71.35,6.55 71.35,7.65 71.16,8.13 70.69,8.35 69.5,8.35 69.38,8.38 69.28,8.47 69.25,8.6 69.25,10.9 69.28,10.97 69.35,11 69.95,11 70.08,11.03 70.17,11.12 70.2,11.25 70.2,12.55 70.23,12.68 70.33,12.77 70.45,12.8 72.45,12.8 72.58,12.77 72.67,12.68 72.7,12.55 72.7,6.55 72.67,6.42 72.58,6.33 72.45,6.3
VCC20_B on BOTTOM: 55.1,2.05 54.98,2.08 54.88,2.17 54.85,2.3 54.85,3.6 54.88,3.73 54.98,3.82 55.1,3.85 57.85,3.85 57.98,3.82 58.07,3.73 58.1,3.6 58.1,2.3 58.07,2.17 57.98,2.08 57.85,2.05
VCC20_B on CONDUCTIVE3: outline of 172 points within 6.05,1 71.25,24 ; 11 cut-outs
VEE_A on TOP: 82.2,43.5 82.11,43.52 82.03,43.57 81.87,43.73 81.69,43.84 81.58,43.85 79.94,43.85 79.9,43.86 79.87,43.88 79.32,44.43 79.21,44.49 79.15,44.5 76.45,44.5 76.33,44.53 76.23,44.62 76.2,44.75 76.2,45 76.23,45.07 76.3,45.1 77.15,45.1 77.36,45.19 77.45,45.4 77.45,46.1 77.48,46.17 77.55,46.2 83.15,46.2 83.24,46.18 83.73,45.69 83.75,45.6 83.75,43.75 83.72,43.62 83.62,43.53 83.5,43.5
VEE_A on TOP: 72.33,45.05 72.27,45.06 72.24,45.1 72.2,45.17 72.15,45.22 72.13,45.25 72.13,45.29 72.13,47.56 72.14,47.63 72.2,47.74 72.33,47.87 72.44,48.05 72.45,48.15 72.45,48.75 72.48,48.82 72.55,48.85 74.7,48.85 74.83,48.82 74.92,48.73 74.95,48.6 74.95,46.5 74.95,46.48 74.91,46.41 74.82,46.39 74.79,46.4 74.75,46.4 73.85,46.4 73.64,46.31 73.55,46.1 73.55,45.3 73.52,45.17 73.42,45.08 73.3,45.05
VEE_A on TOP: 72.59,37.4 72.55,37.41 72.51,37.44 72.45,37.48 72.38,37.5 71.71,37.5 71.65,37.52 71.61,37.57 71.6,37.61 71.6,37.65 71.6,40.7 71.67,40.88 71.85,40.95 76.75,40.95 76.88,40.92 76.97,40.83 77,40.7 77,38.6 76.97,38.48 76.88,38.38 76.75,38.35 76.22,38.35 76.1,38.38 76.01,38.48 75.97,38.6 75.97,39.34 75.89,39.55 75.67,39.63 74.89,39.63 74.67,39.55 74.58,39.34 74.58,38.51 74.58,38.45 74.51,38.34 73.65,37.47 73.6,37.43 73.47,37.4
VEE_A on TOP: outline of 98 points within 24.85,37.45 30.6,43.55
VEE_A on TOP: 37.57,42.94 37.5,42.97 37.47,43.04 37.47,43.2 37.38,43.41 37.17,43.5 34.35,43.5 34.17,43.57 34.1,43.75 34.1,44.25 34.04,44.39 33.9,44.45 33.3,44.45 33.23,44.48 33.2,44.55 33.2,44.7 33.27,44.88 33.45,44.95 34.62,44.95 34.77,44.98 34.9,45.07 34.96,45.12 35,45.12 35.13,45.12 35.24,45.14 35.37,45.2 35.39,45.2 36.82,45.2 36.85,45.2 36.95,45.16 37.03,45.15 37.17,45.15 37.25,45.16 37.35,45.2 37.38,45.2 37.8,45.2 37.98,45.13 38.05,44.95 38.05,44.1 38.12,43.92 38.3,43.85 41.7,43.85 41.88,43.78 41.95,43.6 41.95,43.19 41.88,43.01 41.7,42.94
VEE_A on TOP: 44.15,44.2 44.02,44.23 43.93,44.33 43.9,44.45 43.9,48.27 43.85,48.4 43.73,48.45 43.6,48.4 43.55,48.27 43.55,45.9 43.48,45.72 43.3,45.65 43.23,45.68 43.2,45.75 43.2,46 43.14,46.14 43,46.2 42.76,46.2 42.72,46.21 42.69,46.23 42.54,46.38 42.52,46.41 42.51,46.45 42.51,47.25 42.42,47.46 42.21,47.55 41.75,47.55 41.68,47.58 41.65,47.65 41.65,50.9 41.72,51.08 41.9,51.15 43,51.15 43.18,51.22 43.25,51.4 43.25,56.35 43.32,56.53 43.5,56.6 46.45,56.6 46.63,56.53 46.7,56.35 46.7,51.15 46.73,51.02 46.83,50.93 47.08,50.87 47.17,50.77 47.2,50.65 47.2,50.55 47.17,50.42 47.08,50.33 46.95,50.3 45.65,50.3 45.51,50.24 45.45,50.1 45.45,46.3 45.51,46.16 45.65,46.1 46.6,46.1 46.73,46.07 46.82,45.98 46.85,45.85 46.85,44.45 46.78,44.27 46.6,44.2
VEE_A on BOTTOM: 25.95,54.6 25.77,54.67 25.7,54.85 25.7,57.2 25.77,57.38 25.95,57.45 28.4,57.45 28.47,57.42 28.5,57.35 28.5,56.5 28.57,56.32 28.75,56.25 29.53,56.25 29.6,56.22 29.63,56.15 29.63,55.89 29.62,55.85 29.6,55.82 29.4,55.62 29.35,55.58 29.22,55.55 28.5,55.55 28.1,55.37 27.95,54.95 27.95,54.85 27.92,54.73 27.83,54.63 27.7,54.6
VEE_A on BOTTOM: 44.7,54.4 44.58,54.43 44.48,54.52 44.45,54.65 44.45,55.95 44.48,56.08 44.58,56.17 44.7,56.2 46,56.2 46.12,56.17 46.22,56.08 46.25,55.95 46.25,54.65 46.22,54.52 46.12,54.43 46,54.4
VEE_A on BOTTOM: outline of 201 points within 33.5,41.98 61.35,51.6 ; 1 cut-out
VEE_A on BOTTOM: 34.82,34.95 34.78,34.96 34.74,34.98 33.48,36.24 33.46,36.28 33.45,36.32 33.45,37.5 33.46,37.56 33.48,37.62 33.52,37.66 33.57,37.67 36.62,37.67 36.65,37.67 36.69,37.65 37.19,37.14 37.26,37.09 37.35,37.08 42.1,37.08 42.19,37.09 42.26,37.14 43.72,38.6 43.77,38.64 43.9,38.67 46.08,38.67 46.2,38.64 46.29,38.55 46.33,38.42 46.33,37.62 46.29,37.5 46.2,37.41 46.08,37.38 45.58,37.38 45.15,37.08 45.28,36.58 45.7,36.23 45.71,36.23 45.94,35.99 46.01,35.94 46.1,35.92 47.71,35.92 47.75,35.92 47.78,35.9 47.92,35.75 47.94,35.72 47.95,35.68 47.95,35.2 47.92,35.08 47.83,34.98 47.7,34.95
VEE_A on BOTTOM: outline of 160 points within 51.32,31 84.1,49.75 ; 2 cut-outs
VEE_A on CONDUCTIVE3: outline of 382 points within 12.45,31 84.1,58.95 ; 21 cut-outs
VEE_B on TOP: 56.85,12.7 56.67,12.77 56.6,12.95 56.6,13.8 56.62,13.89 56.66,13.97 56.7,13.99 56.74,14 57.05,14 57.13,14.01 57.23,14.05 57.26,14.05 58.4,14.05 58.58,13.98 58.65,13.8 58.65,12.95 58.58,12.77 58.4,12.7
VEE_B on TOP: outline of 403 points within 14.5,1 96.21,24 ; 4 cut-outs
VEE_B on TOP: 69.55,5.26 69.48,5.29 69.45,5.36 69.45,5.6 69.41,5.73 69.27,5.86 69.25,5.92 69.25,7.8 69.28,7.92 69.38,8.02 69.5,8.05 70.8,8.05 70.92,8.02 71.02,7.92 71.05,7.8 71.05,7.2 71.08,7.08 71.12,7.03 71.32,6.83 71.39,6.71 71.39,6.59 71.32,6.47 71.12,6.27 71.06,6.16 71.05,6.1 71.05,5.51 71.02,5.38 70.92,5.29 70.8,5.26
VEE_B on TOP: 55.52,8.16 55.46,8.18 55.43,8.22 54.97,8.82 54.25,9.05 54.18,9.08 54.15,9.15 54.15,11.35 54.11,11.5 54,11.61 53.97,11.63 53.95,11.74 54.04,11.8 54.45,11.8 54.49,11.79 54.52,11.77 55.58,10.71 55.63,10.63 55.65,10.54 55.65,9.65 55.74,9.44 55.95,9.35 57,9.35 57.18,9.28 57.25,9.1 57.25,8.41 57.18,8.23 57,8.16
VEE_B on TOP: outline of 117 points within 13.7,7.75 25.11,15.05
VEE_B on BOTTOM: outline of 113 points within 22.85,3.9 30.43,11.95
VEE_B on BOTTOM: 23.43,3.1 23.39,3.11 23.36,3.13 20.18,6.31 20.16,6.34 20.15,6.38 20.15,7.33 20.16,7.37 20.18,7.4 20.25,7.47 20.28,7.49 20.32,7.5 20.78,7.5 20.93,7.53 21.06,7.62 21.23,7.79 21.32,7.92 21.35,8.07 21.35,8.75 21.31,8.96 21.19,9.14 20.55,9.77 20.53,9.8 20.52,9.84 20.52,10.2 20.56,10.32 20.65,10.42 20.77,10.45 21.05,10.45 21.22,10.48 21.37,10.58 21.57,10.78 21.6,10.82 21.63,10.85 21.66,10.89 21.71,10.9 22.42,10.9 22.47,10.89 22.51,10.85 22.54,10.81 22.82,10.53 22.83,10.41 22.71,10.37 22.22,10.26 22.14,9.76 22.24,9.55 22.25,9.53 22.25,9.51 22.25,5.75 22.27,5.64 22.34,5.54 24.49,3.39 24.58,3.32 24.7,3.3 24.8,3.2 24.7,3.1
VEE_B on BOTTOM: 75.6,8.4 75.47,8.43 75.38,8.53 75.35,8.65 75.35,11.15 75.38,11.28 75.47,11.37 75.6,11.4 78.4,11.4 78.57,11.33 78.65,11.16 78.65,11.15 78.65,8.87 78.64,8.83 78.62,8.79 78.25,8.43 78.22,8.41 78.18,8.4
VEE_B on BOTTOM: outline of 149 points within 59.81,2.72 90.6,21.15
VEE_B on BOTTOM: outline of 128 points within 28.45,4.97 51.55,13.55
VEE_B on BOTTOM: 40.65,16.98 40.65,17.02 40.65,18.38 40.66,18.42 40.68,18.45 41.99,19.77 42.03,19.79 42.07,19.8 53.63,19.8 53.67,19.79 53.7,19.77 54.79,18.69 54.88,18.62 55,18.6 55.1,18.5 55,18.4 51.17,18.4 51.13,18.41 51.09,18.43 50.41,19.11 50.31,19.18 50.2,19.2 48.85,19.2 48.74,19.18 48.64,19.11 47.85,18.33 47.82,18.31 47.78,18.3 42.39,18.3 42.28,18.28 42.18,18.21 40.81,16.84 40.68,16.82 40.64,16.94
VEE_B on BOTTOM: outline of 241 points within 13.35,1 96.21,24 ; 1 cut-out
VEE_B on BOTTOM: 67.1,15.95 67.03,15.98 67,16.05 67,16.8 66.97,16.93 66.88,17.02 66.75,17.05 66.15,17.05 66.08,17.08 66.05,17.15 66.05,17.8 66.07,17.89 66.11,17.97 66.15,17.99 66.19,18 67.7,18 67.83,17.97 67.92,17.88 67.95,17.75 67.95,16.2 67.92,16.07 67.83,15.98 67.7,15.95
VEE_B on BOTTOM: 56.35,10.2 56.23,10.23 56.13,10.32 56.1,10.45 56.1,12.62 56.11,12.68 56.17,12.8 56.23,12.85 56.36,13.03 56.4,13.25 56.4,14 56.43,14.12 56.52,14.22 56.65,14.25 58.33,14.25 58.45,14.22 58.54,14.12 58.58,14 58.58,11.85 58.55,11.78 58.48,11.75 58.35,11.75 58.21,11.69 58.15,11.55 58.15,11.3 58.12,11.23 58.05,11.2 57.36,11.2 57.35,11.2 57.06,11.13 56.87,10.9 56.77,10.59 56.76,10.57 56.75,10.55 56.43,10.23 56.39,10.21
VEE_B on CONDUCTIVE3: outline of 164 points within 11.45,1 95.85,24 ; 19 cut-outs
DESAT_A on BOTTOM: 7.95,37.25 7.89,37.26 7.78,37.32 7.28,37.82 7.26,37.85 7.25,37.89 7.25,39.55 7.32,39.73 7.5,39.8 16.77,39.8 16.9,39.77 16.99,39.67 17.02,39.55 17.02,39.48 16.99,39.35 16.9,39.26 16.77,39.23 14.72,39.23 14.61,39.2 14.51,39.14 12.7,37.32 12.65,37.28 12.52,37.25
DESAT_B on TOP: 3.9,10.7 3.83,10.73 3.8,10.8 3.8,10.85 3.73,11.03 3.55,11.1 2.65,11.1 2.58,11.13 2.55,11.2 2.55,15.3 2.57,15.39 2.62,15.47 3.03,15.88 3.11,15.93 3.2,15.95 8.3,15.95 8.37,15.92 8.4,15.85 8.4,15.4 8.46,15.26 8.6,15.2 9.2,15.2 9.34,15.26 9.4,15.4 9.4,15.85 9.43,15.92 9.5,15.95 11.55,15.95 11.73,15.88 11.8,15.7 11.8,13.4 11.78,13.31 11.73,13.23 11.58,13.08 11.55,13.06 11.51,13.05 10.9,13.05 10.79,13.03 10.03,12.3 9.95,12.25 9.85,12.23 9.74,12.23 9.59,12.32 9.53,12.48 9.53,12.68 9.4,12.98 9.1,13.12 8.25,13.12 8.23,13.13 8.08,13.18 7.95,13.2 7.56,13.04 7.4,12.65 7.4,11.65 7.33,11.47 7.15,11.4 6.2,11.4 6.02,11.33 5.95,11.15 5.95,10.8 5.92,10.73 5.85,10.7
DESAT_B on BOTTOM: 2.65,10.15 2.68,10.28 2.77,10.37 2.9,10.4 3.3,10.4 3.68,10.78 3.74,10.89 3.75,10.95 3.75,13.95 3.76,14.01 3.82,14.12 4.13,14.43 4.18,14.47 4.3,14.5 6.28,14.5 6.41,14.47 6.5,14.37 6.53,14.25 6.53,12.09 6.53,12.02 6.46,11.91 4.12,9.57 4.07,9.53 3.95,9.5 2.9,9.5 2.77,9.53 2.68,9.62 2.65,9.75
GCLP_EN_A on BOTTOM: 26.05,44.55 26.03,44.63 26.1,44.67 26.5,44.67 26.57,44.63 26.55,44.55 26.35,44.35 26.3,44.33 26.25,44.35
SIG00131 on TOP: 32.11,49.1 31.98,49.13 31.89,49.23 31.86,49.35 31.86,49.75 31.84,49.84 31.8,49.93 31.77,49.96 31.74,49.99 31.32,50.41 31.28,50.46 31.25,50.58 31.25,58 31.28,58.12 31.38,58.22 31.5,58.25 32.85,58.25 32.98,58.22 33.07,58.12 33.1,58 33.1,49.35 33.07,49.23 32.98,49.13 32.85,49.1
SIG00132 on TOP: 39.45,46.6 39.33,46.63 39.23,46.73 39.2,46.85 39.2,57.65 39.23,57.77 39.33,57.87 39.45,57.9 40.9,57.9 41.02,57.87 41.12,57.77 41.15,57.65 41.15,54.55 41.18,54.43 41.22,54.38 41.27,54.33 41.29,54.3 41.3,54.26 41.3,46.85 41.27,46.73 41.17,46.63 41.05,46.6
SIG00133 on BOTTOM: 43.65,50.9 43.52,50.93 43.43,51.02 43.4,51.15 43.4,53.85 43.43,53.98 43.52,54.07 43.65,54.1 46,54.1 46.12,54.07 46.22,53.98 46.25,53.85 46.25,51.15 46.22,51.02 46.12,50.93 46,50.9
SIG00135 on BOTTOM: 40.95,50.6 40.83,50.63 40.73,50.73 40.7,50.85 40.7,54.05 40.73,54.17 40.83,54.27 40.95,54.3 42.15,54.3 42.27,54.27 42.37,54.17 42.4,54.05 42.4,50.85 42.37,50.73 42.27,50.63 42.15,50.6
SIG00137 on BOTTOM: 2.45,37.7 2.33,37.73 2.23,37.83 2.2,37.95 2.2,39.25 2.23,39.38 2.33,39.47 2.45,39.5 6,39.5 6.12,39.47 6.22,39.38 6.25,39.25 6.25,37.95 6.22,37.83 6.12,37.73 6,37.7
SIG00138 on TOP: 2.3,41.25 2.17,41.28 2.08,41.38 2.05,41.5 2.05,44.45 2.08,44.58 2.17,44.67 2.3,44.7 3.7,44.7 3.83,44.67 3.92,44.58 3.95,44.45 3.95,41.5 3.92,41.38 3.83,41.28 3.7,41.25
SIG00138 on BOTTOM: 2.35,40.5 2.23,40.53 2.13,40.62 2.1,40.75 2.1,42.8 2.13,42.92 2.23,43.02 2.35,43.05 3.65,43.05 3.77,43.02 3.87,42.92 3.9,42.8 3.9,40.75 3.87,40.62 3.77,40.53 3.65,40.5
SIG00139 on TOP: 2.4,47.65 2.41,47.71 2.47,47.82 4.03,49.38 4.08,49.42 4.2,49.45 5.85,49.45 5.97,49.42 6.07,49.33 6.1,49.2 6.1,48.2 6.09,48.14 6.03,48.03 4.37,46.37 4.32,46.33 4.2,46.3 2.65,46.3 2.52,46.33 2.43,46.42 2.4,46.55
SIG00140 on TOP: 4.9,52.4 4.91,52.46 4.97,52.57 6.53,54.13 6.58,54.17 6.7,54.2 8.35,54.2 8.47,54.17 8.57,54.08 8.6,53.95 8.6,52.95 8.59,52.89 8.53,52.78 6.87,51.12 6.82,51.08 6.7,51.05 5.15,51.05 5.03,51.08 4.93,51.17 4.9,51.3
SIG00156 on TOP: 61.65,11.45 61.52,11.48 61.43,11.57 61.4,11.7 61.4,12.75 61.43,12.88 61.52,12.97 61.65,13 62,13 62.15,13.03 62.32,13.13 62.35,13.17 63.11,13.93 63.16,13.97 63.29,14 70,14 70.12,13.97 70.22,13.88 70.25,13.75 70.25,12.86 70.22,12.79 70.15,12.76 69.6,12.76 69.51,12.74 69.42,12.7 69.39,12.68 69.18,12.54 69.1,12.3 69.1,11.55 69.07,11.48 69,11.45
SIG00157 on BOTTOM: 2.45,11.4 2.33,11.43 2.23,11.53 2.2,11.65 2.2,14.35 2.23,14.47 2.33,14.57 2.45,14.6 3.25,14.6 3.38,14.57 3.47,14.47 3.5,14.35 3.5,11.65 3.47,11.53 3.38,11.43 3.25,11.4
SIG00158 on TOP: 64.76,2 64.7,2.02 64.19,2.85 63.34,3.15 61.65,3.15 61.52,3.18 61.43,3.27 61.4,3.4 61.4,5.6 61.43,5.67 61.5,5.7 69.2,5.7 69.27,5.67 69.3,5.6 69.3,5.14 69.33,5.01 69.42,4.92 69.55,4.89 72.65,4.89 72.72,4.86 72.75,4.79 72.75,2.25 72.72,2.12 72.62,2.03 72.5,2
SIG00159 on BOTTOM: 63.8,13.95 63.67,13.98 63.58,14.07 63.55,14.2 63.55,16.45 63.58,16.57 63.67,16.67 63.8,16.7 66.6,16.7 66.72,16.67 66.82,16.57 66.85,16.45 66.85,14.2 66.82,14.07 66.72,13.98 66.6,13.95
SIG00161 on BOTTOM: 63.8,11.25 63.67,11.28 63.58,11.38 63.55,11.5 63.55,12.7 63.58,12.82 63.67,12.92 63.8,12.95 66.5,12.95 66.62,12.92 66.72,12.82 66.75,12.7 66.75,11.5 66.72,11.38 66.62,11.28 66.5,11.25
SIG00162 on TOP: 2.3,16.3 2.17,16.33 2.08,16.43 2.05,16.55 2.05,19.55 2.08,19.68 2.17,19.77 2.3,19.8 3.65,19.8 3.77,19.77 3.87,19.68 3.9,19.55 3.9,16.55 3.87,16.43 3.77,16.33 3.65,16.3
SIG00162 on BOTTOM: 2.35,15.6 2.23,15.63 2.13,15.72 2.1,15.85 2.1,18.05 2.13,18.18 2.23,18.27 2.35,18.3 3.65,18.3 3.77,18.27 3.87,18.18 3.9,18.05 3.9,15.85 3.87,15.72 3.77,15.63 3.65,15.6
SIG00163 on TOP: 2.3,21.4 2.17,21.43 2.08,21.52 2.05,21.65 2.05,24.55 2.08,24.68 2.17,24.77 2.3,24.8 3.6,24.8 3.73,24.77 3.82,24.68 3.85,24.55 3.85,21.65 3.82,21.52 3.73,21.43 3.6,21.4
SIG00164 on TOP: 2.3,26.4 2.17,26.43 2.08,26.52 2.05,26.65 2.05,29.55 2.08,29.68 2.17,29.77 2.3,29.8 3.6,29.8 3.73,29.77 3.82,29.68 3.85,29.55 3.85,26.65 3.82,26.52 3.73,26.43 3.6,26.4
SIG00219 on BOTTOM: 31.45,15.5 31.48,15.57 31.55,15.6 32.02,15.6 32.1,15.57 32.12,15.5 32.12,15.47 32.12,15.43 32.1,15.4 31.62,14.92 31.51,14.9 31.45,14.99
VE_A on TOP: 24.2,51.5 24.07,51.53 23.98,51.62 23.95,51.75 23.95,60.75 23.98,60.88 24.07,60.97 24.2,61 32.03,61 32.86,61.35 33.69,61 33.71,61 33.84,60.97 33.93,60.88 33.96,60.75 33.96,60.2 33.91,59.86 33.65,59.43 33.53,59.32 33.42,59.22 33.33,59.09 33.3,58.94 33.3,58.8 33.27,58.73 33.2,58.7 28.59,58.7 28.55,58.7 28.15,58.7 28.12,58.7 27.72,58.93 27.3,59 26.42,58.63 26.05,57.75 26.05,56.55 26.04,56.5 26,56.46 25.8,56.23 25.76,55.92 25.75,55.85 25.75,55.05 25.75,55.05 25.81,54.76 26,54.54 26.15,54.47 26.3,54.45 27.3,54.45 27.77,54.71 27.79,55.35 27.88,55.4 30.07,55.4 30.11,55.39 30.17,55.33 30.18,55.28 30.15,55.05 30.36,54.62 30.85,54.62 30.95,54.63 31,54.54 31,53.65 30.97,53.52 30.88,53.43 30.75,53.4 25.65,53.4 25.52,53.37 25.43,53.27 25.4,53.15 25.4,51.6 25.37,51.53 25.3,51.5
VE_A on TOP: outline of 203 points within 54.91,33.5 99,60.35 ; 1 cut-out
VE_A on TOP: 2.25,31.45 2.12,31.48 2.03,31.57 2,31.7 2,40.85 2.03,40.98 2.12,41.07 2.25,41.1 3.7,41.1 3.9,41.15 4.05,41.3 4.1,41.5 4.1,43.8 4.13,43.87 4.2,43.9 12.3,43.9 12.37,43.87 12.4,43.8 12.41,43.65 12.44,43.52 12.59,43.07 12.6,43.04 12.6,42.35 12.7,42.1 12.95,42 13.1,42 13.17,41.97 13.2,41.9 13.2,41.5 13.17,41.43 13.1,41.4 12.75,41.4 12.61,41.34 12.55,41.2 12.55,41.15 12.52,41.08 12.45,41.05 11.2,41.05 11.17,41.06 11.03,41.13 10.9,41.15 10.41,41.15 10.37,41.16 9.9,41.25 9.43,41.16 9.39,41.15 8.8,41.15 8.62,41.22 8.55,41.4 8.55,41.62 8.48,41.78 8.32,41.85 6.88,41.85 6.72,41.78 6.65,41.62 6.65,41.6 6.62,41.53 6.55,41.5 5.05,41.5 4.97,41.49 4.9,41.45 4.9,31.7 4.87,31.57 4.78,31.48 4.65,31.45
VE_A on TOP: 41.55,52.35 41.48,52.38 41.45,52.45 41.45,54.26 41.43,54.35 41.38,54.44 41.33,54.48 41.31,54.52 41.3,54.55 41.3,56 41.33,56.12 41.42,56.22 41.55,56.25 42.85,56.25 42.98,56.22 43.07,56.12 43.1,56 43.1,52.6 43.07,52.48 42.98,52.38 42.85,52.35
VE_A on BOTTOM: 32.6,55.95 32.48,55.98 32.38,56.07 32.35,56.2 32.35,58.45 32.32,58.58 32.23,58.67 32.1,58.7 29.05,58.7 28.69,58.57 28.47,58.17 28.41,58.15 27.1,58.15 26.98,58.18 26.88,58.27 26.85,58.4 26.85,60.9 26.88,60.97 26.95,61 32.03,61 32.43,61.27 32.9,61.35 33.33,61.25 33.69,61 34,61 34.06,60.99 34.17,60.93 34.52,60.58 34.54,60.55 34.55,60.51 34.55,57.04 34.54,57 34.52,56.97 34.47,56.92 34.41,56.81 34.4,56.74 34.4,56.05 34.37,55.97 34.3,55.95
VE_A on BOTTOM: 5,40.7 4.88,40.73 4.78,40.83 4.75,40.95 4.75,43.65 4.78,43.77 4.88,43.87 5,43.9 11.3,43.9 11.43,43.87 11.52,43.77 11.55,43.65 11.55,40.95 11.52,40.83 11.43,40.73 11.3,40.7
VE_A on BOTTOM: 84.35,31 84.28,31.03 84.25,31.1 84.25,43.71 84.23,43.81 84.18,43.89 78.28,49.78 78.11,49.89 78,49.9 73.55,49.9 73.35,49.85 73.27,49.78 72.92,49.44 72.87,49.35 72.85,49.26 72.85,46.3 72.82,46.17 72.72,46.08 72.6,46.05 68.45,46.05 68.33,46.08 68.23,46.17 68.2,46.3 68.2,55.95 68.16,56.16 68.04,56.34 67.18,57.2 67.16,57.23 67.15,57.27 67.15,60.75 67.22,60.92 67.39,61 67.4,61 74.02,61 74.09,60.97 74.12,60.89 78.08,51.23 88.09,48.25 88.12,48.25 93.93,48.75 98.83,51.91 98.94,51.94 99,51.84 99,31.1 98.97,31.03 98.9,31
VE_A on BOTTOM: 41.55,54.45 41.42,54.48 41.33,54.58 41.3,54.7 41.3,56 41.33,56.12 41.42,56.22 41.55,56.25 42.85,56.25 42.98,56.22 43.07,56.12 43.1,56 43.1,54.7 43.07,54.58 42.98,54.48 42.85,54.45
VE_A on CONDUCTIVE2: 1,51.86 1.06,51.95 1.17,51.93 1.17,51.92 14.77,49.08 22.08,60.89 22.08,60.9 22.11,60.97 22.18,61 31.21,61 31.34,60.97 31.43,60.88 31.46,60.75 31.46,60.2 32.89,58.8 34.26,60.27 34.26,60.29 34.27,60.31 34.36,60.42 34.5,60.46 34.98,60.46 35.05,60.43 35.08,60.35 36.59,58.6 38.27,60.2 38.27,60.75 38.3,60.88 38.4,60.97 38.52,61 74.02,61 74.09,60.97 74.12,60.9 74.1,60.55 74.1,60.2 78.34,51 88.09,48.25 88.12,48.25 93.93,48.75 98.83,51.91 98.94,51.94 99,51.84 99,31.1 98.97,31.03 98.9,31 1.1,31 1.03,31.03 1,31.1 ; 89 cut-outs
VE_A on CONDUCTIVE3: 31,59.1 27,59.1 26.93,59.13 26.9,59.2 26.9,60.9 26.93,60.97 27,61 32.03,61 32.74,61.34 33.5,61.16 33.53,61.12 33.54,61.07 33.54,59.9 33.53,59.83 33.47,59.72 32.92,59.17 32.87,59.13 32.75,59.1 31.03,59.1
VE_A on CONDUCTIVE3: 84.69,31 84.61,31.04 84.59,31.12 84.6,31.18 84.6,31.25 84.6,43.71 84.55,43.94 84.42,44.13 79.38,49.18 79.04,49.37 78.85,49.4 73.3,49.4 72.92,49.3 72.65,49.02 72.55,48.65 72.55,48.2 72.48,48.02 72.3,47.95 68.5,47.95 68.44,47.96 68.33,48.02 67.92,48.43 67.88,48.48 67.85,48.6 67.85,60.31 67.86,60.35 67.88,60.38 68.43,60.93 68.48,60.97 68.6,61 74.02,61 74.09,60.97 74.12,60.89 74.1,60.55 74.1,60.2 78.34,51 88.09,48.25 88.12,48.25 93.93,48.75 98.83,51.91 98.94,51.94 99,51.84 99,31.1 98.97,31.03 98.9,31
VE_A on CONDUCTIVE3: 11.95,34.4 11.92,34.33 11.85,34.3 1.25,34.3 1.12,34.33 1.03,34.42 1,34.55 1,45.5 1.03,45.57 1.1,45.6 11.7,45.6 11.82,45.57 11.92,45.48 11.95,45.35 ; 2 cut-outs
VE_B on TOP: 2.2,7.1 2.08,7.13 1.98,7.22 1.95,7.35 1.95,9.35 1.98,9.47 2.08,9.57 2.2,9.6 3.95,9.6 4.02,9.57 4.05,9.5 4.05,9.35 4.08,9.22 4.17,9.13 4.3,9.1 5.7,9.1 5.83,9.13 5.92,9.22 5.95,9.35 5.95,10.15 5.98,10.28 6.08,10.37 6.2,10.4 7.25,10.4 7.38,10.37 7.47,10.28 7.5,10.15 7.5,7.35 7.47,7.22 7.38,7.13 7.25,7.1
VE_B on TOP: 97.69,5.72 96.47,5.66 96.39,5.68 96.35,5.76 96.35,19.96 96.3,20.19 96.17,20.38 94.78,21.78 94.76,21.81 94.75,21.85 94.75,23.9 94.78,23.97 94.85,24 98.9,24 98.97,23.97 99,23.9 99,5.45 98.95,5.36 98.85,5.36
VE_B on TOP: outline of 103 points within 34.3,1.7 41.3,19.8 ; 1 cut-out
VE_B on TOP: 50.95,4.25 50.83,4.28 50.73,4.38 50.7,4.5 50.7,6.25 50.68,6.34 50.63,6.42 50.52,6.53 50.47,6.61 50.45,6.7 50.45,7.4 50.52,7.57 50.69,7.65 51.4,7.65 51.61,7.74 51.7,7.95 51.7,9.3 51.73,9.37 51.8,9.4 52.96,9.4 53.09,9.37 53.18,9.28 53.21,9.15 53.21,8.53 53.21,8.5 53.2,8.48 53,7.79 53.21,7.1 53.91,6.6 54.76,6.66 54.8,6.67 55.8,6.67 55.92,6.63 56.02,6.54 56.05,6.42 56.05,5.46 56.08,5.33 56.12,5.28 56.17,5.23 56.19,5.2 56.2,5.16 56.2,4.5 56.17,4.38 56.08,4.28 55.95,4.25
VE_B on BOTTOM: 52.64,4.55 52.6,4.56 52.56,4.58 52.51,4.63 52.41,4.7 52.3,4.72 52.05,4.72 51.98,4.75 51.95,4.82 51.95,6.35 51.98,6.47 52.08,6.57 52.2,6.6 57.7,6.6 57.83,6.57 57.92,6.47 57.95,6.35 57.95,4.69 57.94,4.65 57.92,4.61 57.84,4.57 57.75,4.55
VE_B on BOTTOM: outline of 142 points within 1,2.8 13.2,24 ; 1 cut-out
VE_B on BOTTOM: 62.86,0.72 62.84,0.78 62.84,2.3 62.85,2.36 62.91,2.47 63.32,2.88 63.37,2.92 63.49,2.95 65.57,2.95 65.7,2.98 65.75,3.02 66.5,3.78 66.55,3.82 66.68,3.85 69.1,3.85 69.22,3.82 69.32,3.73 69.35,3.6 69.35,3.55 69.38,3.42 69.47,3.33 69.6,3.3 71.25,3.3 71.37,3.33 71.42,3.37 73.83,5.78 73.89,5.89 73.9,5.95 73.9,11.35 73.97,11.53 74.15,11.6 74.95,11.6 75.13,11.53 75.2,11.35 75.2,6.97 75.19,6.94 75.08,6.6 75.1,6.24 75.38,6.02 75.43,5.98 75.45,5.92 75.45,1.25 75.42,1.12 75.33,1.03 75.2,1 64.23,1 63.62,0.63 62.9,0.68
VE_B on CONDUCTIVE2: 99,5.45 98.96,5.37 98.87,5.35 98.85,5.36 94.97,4.9 93.93,1.13 93.92,1.04 93.84,1 64.99,1 64.86,1.03 64.77,1.12 64.74,1.25 64.74,1.8 63.3,3.2 61.94,1.71 61.92,1.64 61.84,1.61 61.37,1.61 61.23,1.65 61.14,1.78 61.13,1.81 59.53,3.4 57.93,1.8 57.93,1.25 57.9,1.12 57.8,1.03 57.68,1 6.16,1 6.08,1.04 6.07,1.13 5.03,4.9 1.15,5.36 1.13,5.35 1.04,5.37 1,5.45 1,23.9 1.03,23.97 1.1,24 98.9,24 98.97,23.97 99,23.9 ; 103 cut-outs
VE_B on CONDUCTIVE3: 1.23,19.07 1.32,19.17 1.45,19.2 5.47,19.2 5.54,19.18 5.84,18.71 6.3,18.55 6.5,18.55 6.75,18.55 6.82,18.52 6.85,18.45 6.85,13.6 6.82,13.47 6.72,13.38 6.6,13.35 5,13.35 4.88,13.38 4.78,13.47 4.75,13.6 4.75,13.75 4.15,14.35 3.55,13.75 3.55,12.75 3.73,12.33 4.15,12.15 6.6,12.15 6.72,12.12 6.82,12.03 6.85,11.9 6.85,5.61 6.82,5.49 6.72,5.4 6.6,5.36 4.37,5.36 4.35,5.37 4.33,5.37 2.84,5.75 1.34,5.45 1.25,5.46 1.2,5.55 1.2,18.95 ; 1 cut-out
VE_B on CONDUCTIVE3: 61.75,1 61.62,1.03 61.53,1.12 61.5,1.25 61.5,3.8 61.51,3.86 61.57,3.97 62.08,4.48 62.13,4.52 62.25,4.55 74.95,4.55 75.01,4.54 75.12,4.48 75.42,4.18 75.44,4.15 75.45,4.11 75.45,1.1 75.42,1.03 75.35,1 64.67,1 64.58,1.05 64.58,1.15 63.34,3.2 62.1,1.15 62.1,1.05 62.01,1
VGATE_A on TOP: 33.05,45.25 32.92,45.28 32.83,45.38 32.8,45.5 32.8,46.4 32.83,46.52 32.92,46.62 33.05,46.65 34.98,46.65 35.1,46.62 35.2,46.52 35.23,46.4 35.23,45.58 35.2,45.5 35.13,45.48 34.95,45.48 34.77,45.43 34.61,45.26 34.56,45.25
VGATE_A on TOP: 34.39,49 34.35,49.01 34.32,49.03 33.67,49.68 33.63,49.73 33.6,49.85 33.6,58.94 33.61,58.98 33.63,59.01 33.7,59.08 33.86,59.22 34,59.39 34.19,59.77 34.26,60.2 34.26,60.75 34.29,60.88 34.38,60.97 34.51,61 35.84,61 36.12,61.21 36.44,61.33 36.46,61.33 36.88,61.33 36.9,61.33 37.22,61.21 37.5,61 38.6,61 38.67,60.97 38.7,60.9 38.7,49.7 38.69,49.64 38.63,49.53 38.13,49.03 38.1,49.01 38.06,49
